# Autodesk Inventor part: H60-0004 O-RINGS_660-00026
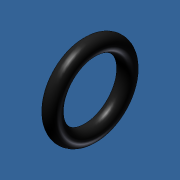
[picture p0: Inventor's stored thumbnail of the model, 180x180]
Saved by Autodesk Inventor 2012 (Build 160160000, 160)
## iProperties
Created: 2013-10
Part Number: H60-0004 O-RINGS_660-00026
Material: Rubber
Document SubType Name: Modeling
Designer: Admin
Density: 0.93 g/cm^3
Mass: 0.154643 g
Surface Area: 2.77138 cm^2
Volume: 0.166283 cm^3
Author: Admin
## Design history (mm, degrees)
node "H60-0004 O-RINGS_660-000261"
node "Base1"
body "Solid1"
